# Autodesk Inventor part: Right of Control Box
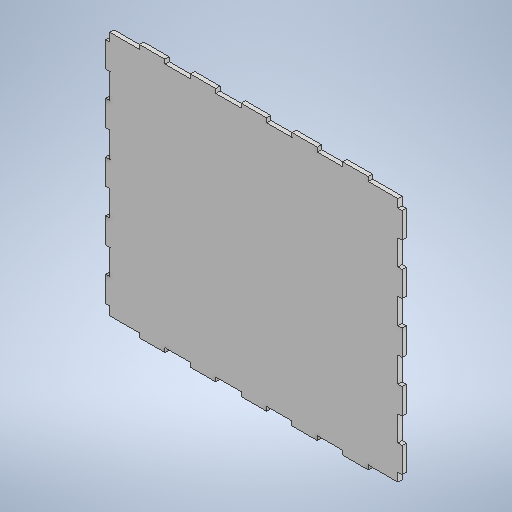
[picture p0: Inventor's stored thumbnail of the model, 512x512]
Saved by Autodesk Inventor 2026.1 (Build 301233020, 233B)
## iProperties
Created: 2026-11
Part Number: Right of Control Box
Material: Generic
Document SubType Name: Modeling
Designer: hp
Density: 1 g/cm^3
Appearance: Default
Author: hp
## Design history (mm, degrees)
sketch "Sketch1"
  geometry: L1 (130, 5)-(130, 0); L2 (130, 5)-(130, 0); L3 (130, 0)-(100, 0); L4 (100, 0)-(100, 5); L5 (130, 0)-(100, 0); L6 (100, 0)-(100, 5); L7 (100, 5)-(130, 5); L8 (100, 5)-(130, 5); L9 (160, 0)-(160, 5); L10 (160, 0)-(160, 5); L11 (190, 0)-(160, 0); L12 (160, 5)-(190, 5); L13 (190, 0)-(160, 0); L14 (160, 5)-(190, 5); L15 (190, 5)-(190, 0); L16 (0, 300)-(350, 300); L17 (350, 300)-(350, 0); L18 (350, 0)-(0, 0); L19 (0, 0)-(0, 300); L20 (70, 5)-(70, 0); L21 (70, 0)-(40, 0); L22 (40, 0)-(40, 5); L23 (40, 5)-(70, 5); L24 (175, 300)-(175, 0); L25 (350, 150)-(0, 150); L26 (220, 0)-(220, 5); L27 (220, 0)-(220, 5); L28 (250, 0)-(220, 0); L29 (250, 0)-(220, 0); L30 (220, 5)-(250, 5); L31 (250, 5)-(250, 0); L32 (280, 0)-(280, 5); L33 (310, 5)-(310, 0); L34 (280, 5)-(310, 5); L35 (310, 0)-(280, 0); L36 (190, 5)-(190, 0); L37 (160, 300)-(160, 295); L38 (160, 300)-(160, 295); L39 (160, 300)-(160, 295); L40 (160, 295)-(190, 295); L41 (160, 295)-(190, 295); L42 (190, 300)-(160, 300); L43 (190, 300)-(160, 300); L44 (190, 295)-(190, 300); L45 (190, 295)-(190, 300); L46 (250, 295)-(250, 300); L47 (220, 300)-(220, 295); L48 (220, 300)-(220, 295); L49 (250, 300)-(220, 300); L50 (220, 295)-(250, 295); L51 (250, 300)-(220, 300); L52 (220, 295)-(250, 295); L53 (250, 295)-(250, 300); L54 (280, 300)-(280, 295); L55 (280, 295)-(310, 295); L56 (310, 300)-(280, 300); L57 (310, 295)-(310, 300); L58 (220, 5)-(250, 5); L59 (250, 5)-(250, 0); L60 (190, 5)-(190, 0); L61 (160, 0)-(160, 5); L62 (190, 0)-(160, 0); L63 (160, 5)-(190, 5); L64 (100, 300)-(100, 295)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; 113 further points
  constraints: 308 end point, 90 symmetric about line, 8 parallel, 6 midpoint, 5 horizontal, 4 perpendicular, 2 vertical, 1 coincident, 1 point on line, 147 other
  dimensions: "d14" = 350 distance of L17.end L18.end; "d15" = 300 distance of L16.end L17.end; "d16" = 30 distance of L9.end L12.end; "d17" = 5 distance of L9.start L9.end; "d18" = 60 distance of L11.start L1.end; "d19" = 60 distance of L11.start L28.start; "d20" = 5 distance of L97.end L96.end; "d21" = 30 distance of L96.end L95.end; "d22" = 60 distance of L95.end L83.end; "d23" = 60 distance of L95.end L107.end; "d24" = 5 distance between parallel lines of L16 L151
extrude "Extrusion2" new body sketch "Sketch1" distance "d25" = 5; taper "d26" = 0 deg
body "Solid2"
node "Sketch Rectangular Pattern2" dims "d18" = 60, "d19" = 60
node "Sketch Rectangular Pattern4" dims "d22" = 60, "d23" = 60
